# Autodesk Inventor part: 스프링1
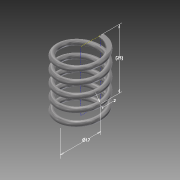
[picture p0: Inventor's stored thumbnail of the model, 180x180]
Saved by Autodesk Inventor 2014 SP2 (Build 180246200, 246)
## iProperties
Created: 2016-03
Part Number: 스프링1
Material: 스테인레스 스틸
Document SubType Name: Modeling
Designer: apexhp001
Density: 8.08 g/cm^3
Appearance: 반연마
Mass: 6.63924 g
Surface Area: 16.7182 cm^2
Volume: 0.821689 cm^3
Author: apexhp001
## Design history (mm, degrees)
sketch "스케치1"
  geometry: L1 (0, 0)-(8.5, 0); L2 (8.5, 0)-(8.5, 20.5); L3 (8.5, 20.5)-(0, 20.5); L4 (0, 20.5)-(0, 0); C1 r 1 at (8.5, 0)
  constraints: 8 end point, 2 parallel, 1 centre point, 1 coincident, 1 horizontal, 1 perpendicular
  dimensions: "d0" = 20.5 distance of L1.end L2.end (derived); "d1" = 17 diameter of L1.end L4; "d2" = 2 diameter of C1
feature "코일1" sketch "스케치1" pitch "d3" = 10; turns "d5" = 5; dims "d4" = 20.5 (= d0), "d6" = 0, angle "d7" = 90 deg, angle "d8" = 90 deg, "d9" = 0, "d10" = 0
sketch "스케치2"
  geometry: L1 (0, 9.5)-(0, 7.5) reference; 1 further point
  constraints: 1 vertical alignment
extrude "돌출1" cut sketch "스케치2" distance "d11" = 10; taper "d12" = 0 deg
node "작업 평면1"
sketch "스케치3"
  geometry: L1 (0, 7.5)-(0, 9.5) reference; 1 further point
  constraints: 1 vertical alignment
extrude "돌출2" cut sketch "스케치3" distance "d14" = 10; taper "d15" = 0 deg
node "솔리드1"
node "절단 모서리 투영1"
node "절단 모서리 투영2"
other parameters: "d13" = 20.5 (= d0)
